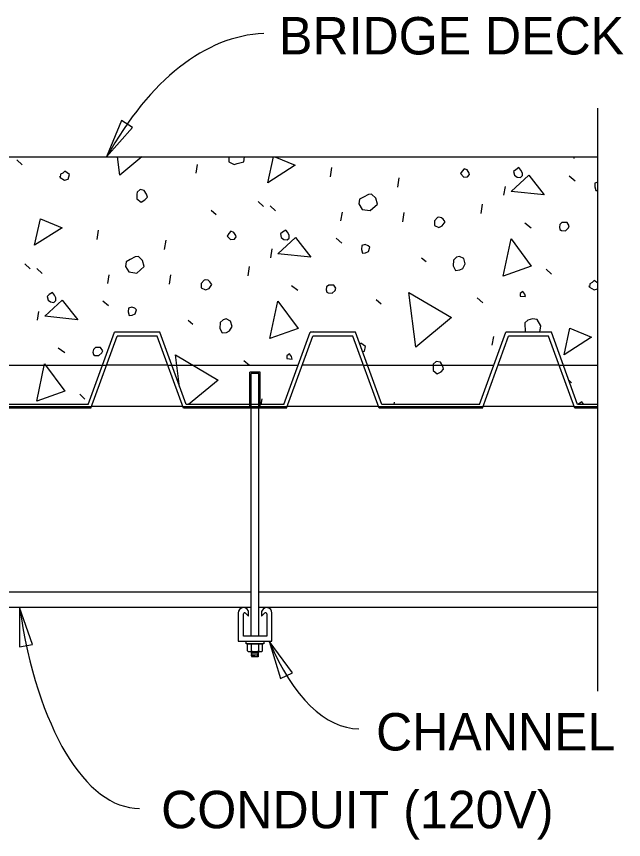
# Model space of a CAD drawing. Extents: x 927736.2 to 927809.6, y 636703.6 to 636757.7.
# Drawn here: x 927797.83 to 927803.88, y 636724.71 to 636732.91 of the extents above; entities that cross this region are included whole.
import ezdxf

# ---------------------------------------------------------------- set-up
doc = ezdxf.new("R2010")
doc.units = 0
for name, color, linetype in [('DimLines_dp', 7, 'Continuous'), ('Miscellaneous1', 7, 'Continuous'), ('Miscellaneous2', 7, 'Continuous'), ('Miscellaneous3', 7, 'Continuous')]:
    doc.layers.add(name, color=color, linetype=linetype)

msp = doc.modelspace()

# ---------------------------------------------------------------- linework, layer by layer
at = {"layer": 'DimLines_dp'}
msp.add_lwpolyline([(927803.6221, 636726.1928), (927803.6221, 636731.9989)], dxfattribs=at)
for points in [[(927798.7324, 636731.5151), (927798.9906, 636731.8085), (927798.8795, 636731.8771)], [(927797.8655, 636727.0244), (927797.8657, 636726.6336), (927797.9944, 636726.6555)], [(927800.3508, 636726.6903), (927800.4651, 636726.3167), (927800.5818, 636726.3752)]]:
    msp.add_lwpolyline(points, close=True, dxfattribs=at)
for centre, major_axis, ratio, start_param, end_param in [((927800.5703, 636726.9054), (0.2741, -5.8397), 0.464296, 3.141604, 3.781059), ((927799.0396, 636727.9386), (0.0188, -2.9139), 0.426092, 5.02876, 6.283138), ((927801.2258, 636728.7323), (0.0188, -2.9139), 0.426092, 5.486066, 6.283138)]:
    msp.add_ellipse(centre, major_axis=major_axis, ratio=ratio, start_param=start_param, end_param=end_param, dxfattribs=at)
at = {"layer": 'Miscellaneous1'}
for p, q in [((927800.1719, 636727.1786), (927797.5209, 636727.1786)), ((927803.6221, 636727.1786), (927800.2488, 636727.1786)), ((927800.1719, 636727.0244), (927797.5209, 636727.0244)), ((927800.0434, 636726.9731), (927800.0434, 636726.6904)), ((927800.0947, 636726.7417), (927800.0947, 636726.9612)), ((927800.1166, 636726.9703), (927800.146, 636726.9409)), ((927800.146, 636726.985), (927800.1407, 636726.9957)), ((927800.146, 636726.9409), (927800.146, 636726.985)), ((927803.6221, 636727.0244), (927800.2488, 636727.0244)), ((927800.28, 636726.9957), (927800.2747, 636726.985)), ((927800.2747, 636726.985), (927800.2747, 636726.9409)), ((927800.2747, 636726.9409), (927800.3041, 636726.9703)), ((927800.326, 636726.9612), (927800.326, 636726.7417)), ((927800.3773, 636726.6904), (927800.3773, 636726.9731)), ((927800.326, 636726.7417), (927800.0947, 636726.7417)), ((927800.0434, 636726.6904), (927800.3773, 636726.6904))]:
    msp.add_line(p, q, dxfattribs=at)
for centre, radius, start, end in [((927800.0947, 636726.9731), 0.0513, 26.17936, 179.9999), ((927800.1075, 636726.9612), 0.0128, 45, 180), ((927800.326, 636726.9731), 0.0513, 0.0001, 153.82064), ((927800.3132, 636726.9612), 0.0128, 360, 135)]:
    msp.add_arc(centre, radius, start, end, dxfattribs=at)
at = {"layer": 'Miscellaneous2'}
for p, q in [((927786.3327, 636731.5153), (927803.6221, 636731.5153)), ((927797.838, 636731.4866), (927797.8897, 636731.4366)), ((927803.3889, 636731.4992), (927803.3917, 636731.5153)), ((927799.6233, 636731.3521), (927799.6383, 636731.4391)), ((927800.9613, 636731.3148), (927800.9746, 636731.4078)), ((927801.6331, 636731.2139), (927801.6465, 636731.3069)), ((927803.3395, 636731.3264), (927803.3971, 636731.278)), ((927802.689, 636731.1329), (927802.704, 636731.22)), ((927800.2414, 636731.0708), (927800.2931, 636731.0208)), ((927799.7731, 636730.9837), (927799.8232, 636730.9396)), ((927800.3618, 636731.0265), (927800.4135, 636730.9765)), ((927802.4632, 636730.9511), (927802.4766, 636731.0441)), ((927801.0658, 636730.8768), (927801.0808, 636730.9638)), ((927801.6808, 636730.8692), (927801.6942, 636730.9621)), ((927802.8971, 636730.8567), (927802.9607, 636730.8099)), ((927798.6382, 636730.6923), (927798.6516, 636730.7853)), ((927799.31, 636730.5915), (927799.3234, 636730.6844)), ((927801.0164, 636730.7039), (927801.0741, 636730.6555)), ((927800.366, 636730.5105), (927800.381, 636730.5975)), ((927801.8663, 636730.5103), (927801.9148, 636730.4722)), ((927797.9183, 636730.4484), (927797.97, 636730.3984)), ((927798.0387, 636730.404), (927798.0904, 636730.354)), ((927800.1402, 636730.3287), (927800.1536, 636730.4217)), ((927798.7428, 636730.2543), (927798.7578, 636730.3413)), ((927799.3577, 636730.2467), (927799.3711, 636730.3397)), ((927803.1098, 636730.3966), (927803.1615, 636730.3466)), ((927800.5741, 636730.2343), (927800.6377, 636730.1875)), ((927798.6934, 636730.0815), (927798.751, 636730.0331)), ((927801.4156, 636730.0958), (927801.4657, 636730.0518)), ((927802.4205, 636730.1098), (927802.4782, 636730.0614)), ((927798.0429, 636729.888), (927798.0579, 636729.975)), ((927799.5433, 636729.8878), (927799.5918, 636729.8498)), ((927798.5471, 636729.0485), (927798.809, 636729.7682)), ((927799.2612, 636729.7682), (927798.809, 636729.7682)), ((927799.5231, 636729.0485), (927799.2612, 636729.7682)), ((927800.4968, 636729.0485), (927800.7588, 636729.7682)), ((927801.2109, 636729.7682), (927800.7588, 636729.7682)), ((927800.7867, 636729.7741), (927800.7929, 636729.7682)), ((927801.4728, 636729.0485), (927801.2109, 636729.7682)), ((927802.4466, 636729.0485), (927802.7085, 636729.7682)), ((927803.1607, 636729.7682), (927802.7085, 636729.7682)), ((927803.4226, 636729.0485), (927803.1607, 636729.7682)), ((927798.574, 636729.01), (927798.836, 636729.7297)), ((927799.2342, 636729.7297), (927798.836, 636729.7297)), ((927799.4962, 636729.01), (927799.2342, 636729.7297)), ((927800.5238, 636729.01), (927800.7857, 636729.7297)), ((927801.184, 636729.7297), (927800.7857, 636729.7297)), ((927801.4459, 636729.01), (927801.184, 636729.7297)), ((927802.4735, 636729.01), (927802.7355, 636729.7297)), ((927802.572, 636729.6396), (927802.587, 636729.7266)), ((927803.1337, 636729.7297), (927802.7355, 636729.7297)), ((927803.3957, 636729.01), (927803.1337, 636729.7297)), ((927798.251, 636729.6118), (927798.3146, 636729.565)), ((927800.0975, 636729.4873), (927800.1551, 636729.4389)), ((927800.2617, 636729.3696), (927800.159, 636729.3696)), ((927800.159, 636729.01), (927800.159, 636729.3696)), ((927800.2488, 636729.3568), (927800.1719, 636729.3568)), ((927800.2617, 636729.01), (927800.2617, 636729.3696)), ((927803.3344, 636729.2909), (927803.3622, 636729.264)), ((927798.4637, 636729.1517), (927798.5154, 636729.1017)), ((927800.2715, 636729.0485), (927800.2811, 636729.1042)), ((927798.574, 636729.01), (927797.5464, 636729.01)), ((927798.5471, 636729.0485), (927797.5733, 636729.0485)), ((927799.4893, 636729.0288), (927799.6693, 636729.0288)), ((927800.5238, 636729.01), (927799.4962, 636729.01)), ((927800.4968, 636729.0485), (927799.5231, 636729.0485)), ((927801.439, 636729.0288), (927801.619, 636729.0288)), ((927802.4735, 636729.01), (927801.4459, 636729.01)), ((927802.4466, 636729.0485), (927801.4728, 636729.0485)), ((927801.5968, 636729.0485), (927801.6003, 636729.0728)), ((927803.3888, 636729.0288), (927803.5688, 636729.0288)), ((927803.6221, 636729.01), (927803.3957, 636729.01)), ((927803.6221, 636729.0485), (927803.4226, 636729.0485))]:
    msp.add_line(p, q, dxfattribs=at)
for points in [[(927798.8623, 636731.3333), (927798.8392, 636731.5153)], [(927799.083, 636731.5153), (927798.8623, 636731.3333)], [(927799.949, 636731.5153), (927799.9505, 636731.4653), (927800.0018, 636731.4408), (927800.0316, 636731.4487), (927800.0971, 636731.4663), (927800.1037, 636731.5153)], [(927800.3385, 636731.2565), (927800.3942, 636731.5153)], [(927800.4083, 636731.5153), (927800.6108, 636731.4316), (927800.3385, 636731.2565)], [(927802.2546, 636731.3485), (927802.2896, 636731.3132), (927802.3269, 636731.3168), (927802.346, 636731.3411), (927802.3428, 636731.353), (927802.3213, 636731.3855), (927802.2927, 636731.397), (927802.2736, 636731.3728), (927802.2546, 636731.3485)], [(927802.7948, 636731.3337), (927802.8191, 636731.3146), (927802.8521, 636731.3107), (927802.8727, 636731.329), (927802.8723, 636731.3544), (927802.8583, 636731.3826), (927802.8384, 636731.4092), (927802.8059, 636731.3877), (927802.7853, 636731.3694), (927802.7948, 636731.3337)], [(927798.2688, 636731.3084), (927798.3141, 636731.2822), (927798.3499, 636731.2918), (927798.3625, 636731.3399), (927798.3156, 636731.372), (927798.295, 636731.3537), (927798.2728, 636731.3414), (927798.2688, 636731.3084), (927798.2656, 636731.3203)], [(927802.7617, 636731.1716), (927802.9355, 636731.333), (927803.0898, 636731.1382), (927802.7617, 636731.1716)], [(927803.6221, 636731.2617), (927803.595, 636731.2544), (927803.5926, 636731.2155)], [(927799.0345, 636731.1433), (927799.0338, 636731.0984), (927799.0747, 636731.0647), (927799.1132, 636731.0878), (927799.1382, 636731.1136), (927799.1302, 636731.1434), (927799.1071, 636731.1819), (927799.0666, 636731.1902), (927799.0357, 636731.1627), (927799.0345, 636731.1433)], [(927801.244, 636731.0458), (927801.2778, 636730.991), (927801.3573, 636730.9804), (927801.4295, 636731.0444), (927801.4136, 636731.104), (927801.371, 636731.1437), (927801.3396, 636731.1417), (927801.2892, 636731.1154), (927801.2507, 636731.0923), (927801.244, 636731.0458)], [(927803.5926, 636731.2155), (927803.6022, 636731.1797), (927803.6221, 636731.181)], [(927798.0154, 636730.634), (927798.0723, 636730.8982), (927798.2877, 636730.8091), (927798.0154, 636730.634)], [(927801.9978, 636730.8775), (927801.997, 636730.8326), (927802.0407, 636730.8124), (927802.0749, 636730.8279), (927802.1026, 636730.8673), (927802.0827, 636730.8939), (927802.066, 636730.9086), (927802.039, 636730.9141), (927802.0271, 636730.9109), (927801.9978, 636730.8775)], [(927803.2467, 636730.7908), (927803.2619, 636730.7821), (927803.3008, 636730.7797), (927803.3317, 636730.8072), (927803.3389, 636730.8283), (927803.3174, 636730.8608), (927803.2665, 636730.8599), (927803.2459, 636730.8417), (927803.2404, 636730.8146), (927803.2467, 636730.7908)], [(927799.9315, 636730.7261), (927799.9665, 636730.6907), (927800.0039, 636730.6944), (927800.0229, 636730.7186), (927800.0197, 636730.7305), (927799.9982, 636730.7631), (927799.9696, 636730.7746), (927799.9506, 636730.7503), (927799.9315, 636730.7261)], [(927800.4718, 636730.7112), (927800.496, 636730.6922), (927800.529, 636730.6882), (927800.5497, 636730.7065), (927800.5492, 636730.732), (927800.5353, 636730.7602), (927800.5154, 636730.7867), (927800.4828, 636730.7653), (927800.4622, 636730.747), (927800.4718, 636730.7112)], [(927800.4386, 636730.5491), (927800.6124, 636730.7106), (927800.7668, 636730.5157), (927800.4386, 636730.5491)], [(927802.6816, 636730.3266), (927802.7606, 636730.6989), (927802.9612, 636730.427), (927802.6816, 636730.3266)], [(927801.2696, 636730.593), (927801.2791, 636730.5573), (927801.3105, 636730.5593), (927801.3387, 636730.5732), (927801.353, 636730.6153), (927801.3363, 636730.63), (927801.3076, 636730.6415), (927801.2719, 636730.6319), (927801.2696, 636730.593)], [(927798.921, 636730.4234), (927798.9548, 636730.3686), (927799.0342, 636730.3579), (927799.1065, 636730.422), (927799.0905, 636730.4816), (927799.0479, 636730.5212), (927799.0166, 636730.5192), (927798.9662, 636730.4929), (927798.9276, 636730.4698), (927798.921, 636730.4234)], [(927802.1853, 636730.4872), (927802.1818, 636730.4288), (927802.2065, 636730.3844), (927802.2498, 636730.3896), (927802.278, 636730.4035), (927802.3041, 636730.4489), (927802.2898, 636730.5025), (927802.246, 636730.5227), (927802.2163, 636730.5147), (927802.1853, 636730.4872)], [(927799.6747, 636730.255), (927799.674, 636730.2101), (927799.7177, 636730.1899), (927799.7518, 636730.2055), (927799.7796, 636730.2448), (927799.7597, 636730.2714), (927799.743, 636730.2861), (927799.716, 636730.2916), (927799.7041, 636730.2884), (927799.6747, 636730.255)], [(927800.9237, 636730.1683), (927800.9388, 636730.1596), (927800.9777, 636730.1573), (927801.0087, 636730.1847), (927801.0158, 636730.2058), (927800.9943, 636730.2383), (927800.9435, 636730.2375), (927800.9228, 636730.2192), (927800.9173, 636730.1922), (927800.9237, 636730.1683)], [(927803.6221, 636730.2582), (927803.5874, 636730.282), (927803.5668, 636730.2637), (927803.5445, 636730.2513), (927803.5406, 636730.2184), (927803.5374, 636730.2303)], [(927798.1487, 636730.0888), (927798.173, 636730.0697), (927798.206, 636730.0658), (927798.2266, 636730.0841), (927798.2262, 636730.1095), (927798.2122, 636730.1377), (927798.1923, 636730.1643), (927798.1598, 636730.1428), (927798.1392, 636730.1245), (927798.1487, 636730.0888)], [(927801.811, 636729.6208), (927801.742, 636730.1642), (927802.1665, 636729.914), (927801.811, 636729.6208)], [(927802.8495, 636730.1289), (927802.902, 636730.1238), (927802.8956, 636730.1477), (927802.8757, 636730.1743), (927802.8491, 636730.1544), (927802.8495, 636730.1289)], [(927803.5406, 636730.2184), (927803.5859, 636730.1922), (927803.6216, 636730.2018), (927803.6221, 636730.2035)], [(927798.1156, 636729.9266), (927798.2894, 636730.0881), (927798.4437, 636729.8933), (927798.1156, 636729.9266)], [(927800.3586, 636729.7041), (927800.4376, 636730.0764), (927800.6381, 636729.8045), (927800.3586, 636729.7041)], [(927798.9465, 636729.9705), (927798.9561, 636729.9348), (927798.9875, 636729.9368), (927799.0157, 636729.9508), (927799.0299, 636729.9929), (927799.0132, 636730.0076), (927798.9846, 636730.019), (927798.9489, 636730.0095), (927798.9465, 636729.9705)], [(927799.8623, 636729.8648), (927799.8588, 636729.8064), (927799.8834, 636729.7619), (927799.9267, 636729.7671), (927799.9549, 636729.7811), (927799.9811, 636729.8264), (927799.9667, 636729.88), (927799.923, 636729.9002), (927799.8932, 636729.8922), (927799.8623, 636729.8648)], [(927803.0477, 636729.7682), (927803.0564, 636729.8333), (927803.021, 636729.894), (927802.9745, 636729.9007), (927802.9269, 636729.8879), (927802.8959, 636729.8605)], [(927802.8959, 636729.8605), (927802.8987, 636729.7682)], [(927803.2872, 636729.5439), (927803.3441, 636729.8082), (927803.5595, 636729.7191), (927803.2872, 636729.5439)], [(927798.6006, 636729.5459), (927798.6157, 636729.5372), (927798.6547, 636729.5348), (927798.6856, 636729.5623), (927798.6928, 636729.5833), (927798.6713, 636729.6159), (927798.6204, 636729.615), (927798.5998, 636729.5967), (927798.5943, 636729.5697), (927798.6006, 636729.5459)], [(927801.2813, 636729.5747), (927801.2986, 636729.5793), (927801.3112, 636729.6274), (927801.2643, 636729.6595), (927801.2538, 636729.6502)], [(927799.4593, 636729.2238), (927799.4189, 636729.5417), (927799.8435, 636729.2916), (927799.5487, 636729.0485)], [(927800.5265, 636729.5065), (927800.5789, 636729.5014), (927800.5725, 636729.5252), (927800.5526, 636729.5518), (927800.526, 636729.5319), (927800.5265, 636729.5065)], [(927798.0355, 636729.0816), (927798.1145, 636729.4539), (927798.3151, 636729.1821), (927798.0355, 636729.0816)], [(927801.9832, 636729.4308), (927801.9825, 636729.3859), (927802.0234, 636729.3522), (927802.0619, 636729.3752), (927802.0869, 636729.4011), (927802.0789, 636729.4309), (927802.0558, 636729.4694), (927802.0153, 636729.4777), (927801.9844, 636729.4502), (927801.9832, 636729.4308)], [(927803.4834, 636729.0485), (927803.4641, 636729.0742), (927803.4316, 636729.0527), (927803.4267, 636729.0485)]]:
    msp.add_lwpolyline(points, dxfattribs=at)
at = {"layer": 'Miscellaneous3'}
for p, q in [((927797.3899, 636729.4401), (927798.7306, 636729.4401)), ((927799.3396, 636729.4401), (927798.7306, 636729.4401)), ((927799.3396, 636729.4401), (927800.6394, 636729.4401)), ((927801.2894, 636729.4401), (927800.6803, 636729.4401)), ((927801.2894, 636729.4401), (927802.5891, 636729.4401)), ((927803.2391, 636729.4401), (927802.6301, 636729.4401)), ((927803.2391, 636729.4401), (927803.6221, 636729.4401)), ((927800.1719, 636726.7417), (927800.1719, 636729.3568)), ((927800.2488, 636726.7417), (927800.2488, 636729.3568)), ((927797.5395, 636729.0288), (927798.5809, 636729.0288)), ((927799.4893, 636729.0288), (927798.5809, 636729.0288)), ((927799.4893, 636729.0288), (927800.5306, 636729.0288)), ((927801.4391, 636729.0288), (927800.5306, 636729.0288)), ((927801.439, 636729.0288), (927802.4804, 636729.0288)), ((927803.3888, 636729.0288), (927802.4804, 636729.0288)), ((927803.3888, 636729.0288), (927803.6221, 636729.0288)), ((927800.1361, 636726.5929), (927800.1361, 636726.6629)), ((927800.1361, 636726.6629), (927800.2845, 636726.6629)), ((927800.1732, 636726.5929), (927800.1732, 636726.6629)), ((927800.2474, 636726.5929), (927800.2474, 636726.6629)), ((927800.2845, 636726.5929), (927800.2845, 636726.6629)), ((927800.1546, 636726.5874), (927800.2659, 636726.5874)), ((927800.1717, 636726.586), (927800.188, 636726.5874)), ((927800.1717, 636726.586), (927800.1743, 636726.5874)), ((927800.1847, 636726.5806), (927800.1717, 636726.586)), ((927800.1717, 636726.5732), (927800.1847, 636726.5806)), ((927800.1717, 636726.5732), (927800.2488, 636726.5799)), ((927800.1847, 636726.5678), (927800.1717, 636726.5732)), ((927800.1717, 636726.5605), (927800.1847, 636726.5678)), ((927800.1717, 636726.5605), (927800.2488, 636726.567)), ((927800.1847, 636726.5551), (927800.1717, 636726.5605)), ((927800.1717, 636726.5476), (927800.1847, 636726.5551)), ((927800.1717, 636726.5476), (927800.2488, 636726.5543)), ((927800.1847, 636726.5422), (927800.1717, 636726.5476)), ((927800.2358, 636726.5851), (927800.2398, 636726.5874)), ((927800.2488, 636726.5799), (927800.2358, 636726.5851)), ((927800.2358, 636726.5723), (927800.2488, 636726.5799)), ((927800.2488, 636726.567), (927800.2358, 636726.5723)), ((927800.2358, 636726.5596), (927800.2488, 636726.567)), ((927800.2488, 636726.5543), (927800.2358, 636726.5596)), ((927800.2358, 636726.5467), (927800.2488, 636726.5543)), ((927800.2488, 636726.5414), (927800.2358, 636726.5467)), ((927800.1762, 636726.5375), (927800.1847, 636726.5422)), ((927800.1762, 636726.5375), (927800.2417, 636726.5375)), ((927800.2011, 636726.5375), (927800.2488, 636726.5414)), ((927800.2417, 636726.5375), (927800.2488, 636726.5414))]:
    msp.add_line(p, q, dxfattribs=at)
msp.add_lwpolyline([(927800.2973, 636726.6904), (927800.2973, 636726.6629), (927800.1233, 636726.6629), (927800.1233, 636726.6904)], close=True, dxfattribs=at)
for centre, radius, start, end in [((927800.1546, 636726.6215), 0.034, 236.97907, 303.02093), ((927800.2103, 636726.7154), 0.1279, 253.13957, 286.86043), ((927800.2659, 636726.6215), 0.034, 236.97907, 303.02093)]:
    msp.add_arc(centre, radius, start, end, dxfattribs=at)

# ---------------------------------------------------------------- texts
at = {"layer": 'DimLines_dp'}
for s, height, p in [('BRIDGE DECK', 0.372961, (927800.4488, 636732.5357)), ('CHANNEL', 0.37296, (927801.4153, 636725.601)), ('CONDUIT (120V)', 0.372961, (927799.2752, 636724.8261))]:
    msp.add_text(s, height=height, dxfattribs=at).set_placement(p)

doc.saveas('drawing.dxf')
